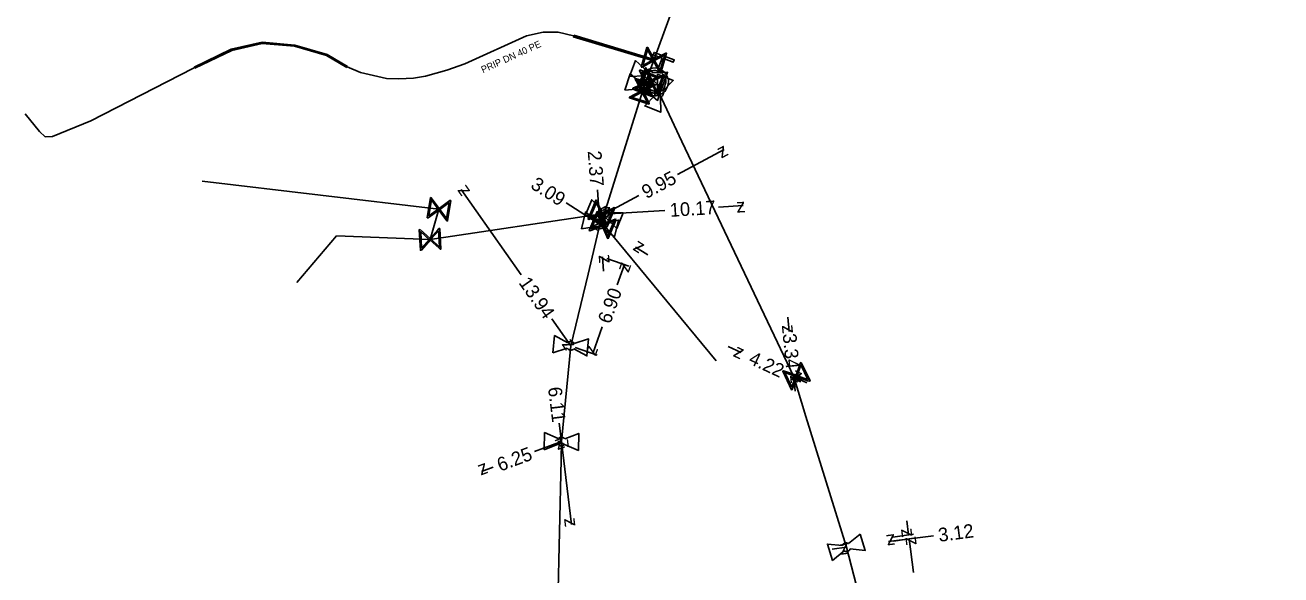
# Model space of a CAD drawing. Extents: x -638315 to -636370, y -1116147 to -1115110.
# Drawn here: x -637156.1 to -637064.4, y -1115769.8 to -1115729.6 of the extents above; entities that cross this region are included whole.
import ezdxf

# ---------------------------------------------------------------- set-up
doc = ezdxf.new("R2010")
doc.units = 0
for name, color, linetype in [('Default', 7, 'Continuous'), ('VP Chránička', 7, 'Continuous'), ('VP Chránička - okraje', 7, 'Continuous'), ('VP Hydrant', 7, 'Continuous'), ('VP Kótování', 7, 'Continuous'), ('VP Lomový bod', 7, 'Continuous'), ('VP Popis přípojky', 7, 'Continuous'), ('VP Přípojka', 7, 'Continuous'), ('VP Řad', 7, 'Continuous'), ('VP Šoupě', 7, 'Continuous')]:
    doc.layers.add(name, color=color, linetype=linetype)

msp = doc.modelspace()

# ---------------------------------------------------------------- linework, layer by layer
at = {"layer": 'Default'}
for points in [[(-637109.703, -1115732.85), (-637109.377, -1115733.004), (-637109.227, -1115733.338), (-637109.058, -1115733.715), (-637109.205, -1115734.104), (-637109.351, -1115734.492), (-637109.728, -1115734.662), (-637110.105, -1115734.832), (-637110.494, -1115734.685), (-637110.88, -1115734.54), (-637111.051, -1115734.164), (-637111.222, -1115733.787), (-637111.076, -1115733.4), (-637110.93, -1115733.01), (-637110.554, -1115732.839), (-637110.221, -1115732.685), (-637109.875, -1115732.786)], [(-637109.855, -1115732.987), (-637110.171, -1115732.868), (-637110.477, -1115733.007), (-637110.782, -1115733.145), (-637110.901, -1115733.462), (-637111.02, -1115733.778), (-637110.882, -1115734.083), (-637110.743, -1115734.389), (-637110.427, -1115734.508), (-637110.113, -1115734.626), (-637109.806, -1115734.488), (-637109.5, -1115734.35), (-637109.381, -1115734.034), (-637109.262, -1115733.718), (-637109.4, -1115733.412), (-637109.539, -1115733.106), (-637109.855, -1115732.987)], [(-637110.417, -1115733.483), (-637110.463, -1115733.509), (-637110.517, -1115733.518), (-637110.6, -1115733.531), (-637110.677, -1115733.503), (-637110.754, -1115733.475), (-637110.81, -1115733.409), (-637110.845, -1115733.369), (-637110.863, -1115733.32)], [(-637110.723, -1115732.935), (-637110.677, -1115732.911), (-637110.625, -1115732.901), (-637110.539, -1115732.888), (-637110.463, -1115732.916), (-637110.386, -1115732.944), (-637110.331, -1115733.009), (-637110.296, -1115733.05), (-637110.277, -1115733.1)], [(-637110.754, -1115734.405), (-637110.799, -1115734.434), (-637110.853, -1115734.445), (-637110.935, -1115734.463), (-637111.013, -1115734.439), (-637111.091, -1115734.414), (-637111.15, -1115734.351), (-637111.187, -1115734.313), (-637111.208, -1115734.264)], [(-637111.086, -1115733.874), (-637111.042, -1115733.847), (-637110.989, -1115733.835), (-637110.905, -1115733.818), (-637110.827, -1115733.842), (-637110.749, -1115733.866), (-637110.691, -1115733.928), (-637110.654, -1115733.968), (-637110.633, -1115734.016)], [(-637110.087, -1115734.725), (-637110.112, -1115734.678), (-637110.119, -1115734.624), (-637110.131, -1115734.54), (-637110.101, -1115734.464), (-637110.071, -1115734.388), (-637110.003, -1115734.334), (-637109.962, -1115734.3), (-637109.912, -1115734.283)], [(-637109.532, -1115734.434), (-637109.508, -1115734.48), (-637109.5, -1115734.533), (-637109.49, -1115734.619), (-637109.52, -1115734.695), (-637109.55, -1115734.771), (-637109.616, -1115734.824), (-637109.658, -1115734.858), (-637109.708, -1115734.875)], [(-637113.675, -1115743.697), (-637113.722, -1115743.721), (-637113.776, -1115743.727), (-637113.86, -1115743.738), (-637113.935, -1115743.707), (-637114.011, -1115743.675), (-637114.064, -1115743.607), (-637114.097, -1115743.565), (-637114.113, -1115743.515)], [(-637113.957, -1115743.137), (-637113.91, -1115743.114), (-637113.857, -1115743.107), (-637113.771, -1115743.098), (-637113.696, -1115743.129), (-637113.62, -1115743.16), (-637113.569, -1115743.227), (-637113.535, -1115743.27), (-637113.519, -1115743.32)], [(-637113.942, -1115744.418), (-637113.985, -1115744.449), (-637114.037, -1115744.464), (-637114.118, -1115744.487), (-637114.198, -1115744.468), (-637114.277, -1115744.449), (-637114.341, -1115744.39), (-637114.38, -1115744.354), (-637114.404, -1115744.307)], [(-637114.308, -1115743.909), (-637114.266, -1115743.879), (-637114.214, -1115743.864), (-637114.131, -1115743.841), (-637114.051, -1115743.86), (-637113.972, -1115743.879), (-637113.91, -1115743.937), (-637113.87, -1115743.974), (-637113.847, -1115744.021)], [(-637116.477, -1115752.803), (-637116.439, -1115752.767), (-637116.391, -1115752.745), (-637116.311, -1115752.711), (-637116.23, -1115752.719), (-637116.148, -1115752.727), (-637116.08, -1115752.775), (-637116.035, -1115752.806), (-637116.005, -1115752.85)], [(-637116.044, -1115753.256), (-637116.082, -1115753.292), (-637116.132, -1115753.315), (-637116.209, -1115753.349), (-637116.29, -1115753.341), (-637116.372, -1115753.333), (-637116.443, -1115753.283), (-637116.487, -1115753.253), (-637116.517, -1115753.21)], [(-637117.174, -1115759.81), (-637117.139, -1115759.771), (-637117.092, -1115759.746), (-637117.015, -1115759.706), (-637116.933, -1115759.707), (-637116.852, -1115759.709), (-637116.779, -1115759.752), (-637116.732, -1115759.78), (-637116.699, -1115759.821)], [(-637116.708, -1115760.229), (-637116.743, -1115760.268), (-637116.791, -1115760.294), (-637116.865, -1115760.334), (-637116.947, -1115760.332), (-637117.029, -1115760.331), (-637117.104, -1115760.286), (-637117.149, -1115760.26), (-637117.183, -1115760.218)], [(-637096.416, -1115767.615), (-637096.395, -1115767.566), (-637096.358, -1115767.526), (-637096.3, -1115767.465), (-637096.222, -1115767.441), (-637096.144, -1115767.417), (-637096.059, -1115767.435), (-637096.007, -1115767.446), (-637095.963, -1115767.475)], [(-637095.842, -1115767.865), (-637095.863, -1115767.913), (-637095.899, -1115767.952), (-637095.959, -1115768.014), (-637096.038, -1115768.038), (-637096.116, -1115768.062), (-637096.198, -1115768.044), (-637096.251, -1115768.033), (-637096.296, -1115768.004)]]:
    msp.add_open_spline(points, degree=3, dxfattribs=at)
at = {"layer": 'VP Chránička'}
for points in [[(-637110.19, -1115732.169), (-637116.06, -1115730.4)], [(-637132.58, -1115732.66), (-637134.08, -1115731.79), (-637136.42, -1115731.11), (-637138.79, -1115730.91), (-637141.04, -1115731.41), (-637143.74, -1115732.71)]]:
    msp.add_lwpolyline(points, dxfattribs=at)
at = {"layer": 'VP Chránička - okraje'}
for points in [[(-637110.206, -1115732.222), (-637116.076, -1115730.453)], [(-637116.044, -1115730.347), (-637110.174, -1115732.116)], [(-637143.76, -1115732.669), (-637141.055, -1115731.367), (-637138.793, -1115730.865), (-637136.412, -1115731.066), (-637134.062, -1115731.748), (-637132.557, -1115732.621)], [(-637132.603, -1115732.699), (-637134.098, -1115731.832), (-637136.428, -1115731.154), (-637138.787, -1115730.955), (-637141.025, -1115731.453), (-637143.72, -1115732.751)]]:
    msp.add_lwpolyline(points, dxfattribs=at)
at = {"layer": 'VP Hydrant'}
msp.add_lwpolyline([(-637109.875, -1115732.786), (-637109.586, -1115732.018), (-637110.231, -1115731.775), (-637110.167, -1115731.603), (-637108.704, -1115732.154), (-637108.769, -1115732.325), (-637109.414, -1115732.083), (-637109.703, -1115732.85)], dxfattribs=at)
at = {"layer": 'VP Kótování'}
for points in [[(-637108.455, -1115740.523), (-637105.06, -1115738.69)], [(-637119.892, -1115747.856), (-637124.268, -1115741.62)], [(-637114.312, -1115741.63), (-637114.125, -1115744.164)], [(-637116.584, -1115742.592), (-637114.125, -1115744.164)], [(-637111.279, -1115742.048), (-637113.816, -1115743.418)], [(-637109.376, -1115743.139), (-637113.816, -1115743.418)], [(-637105.475, -1115742.894), (-637103.67, -1115742.78)], [(-637110.635, -1115746.396), (-637111.52, -1115745.83)], [(-637113.873, -1115747.577), (-637113.95, -1115746.53)], [(-637113.62, -1115746.647), (-637112.015, -1115747.218)], [(-637112.867, -1115748.57), (-637112.344, -1115747.101)], [(-637100.404, -1115750.935), (-637100.3, -1115751.98)], [(-637117.646, -1115751.055), (-637116.26, -1115753.03)], [(-637113.96, -1115751.645), (-637114.654, -1115753.601)], [(-637115.93, -1115753.147), (-637114.325, -1115753.718)], [(-637104.752, -1115753.077), (-637103.8, -1115753.52)], [(-637099.867, -1115756.346), (-637099.971, -1115755.301)], [(-637099.019, -1115755.744), (-637099.971, -1115755.301)], [(-637117.103, -1115758.688), (-637116.94, -1115760.02)], [(-637118.912, -1115760.758), (-637116.94, -1115760.02)], [(-637116.94, -1115760.02), (-637116.2, -1115766.08)], [(-637121.919, -1115761.884), (-637122.79, -1115762.21)], [(-637091.723, -1115765.8), (-637091.584, -1115766.841)], [(-637089.763, -1115766.901), (-637093.041, -1115767.333)], [(-637092.733, -1115766.994), (-637091.237, -1115766.795)], [(-637092.694, -1115767.287), (-637091.198, -1115767.088)], [(-637091.22, -1115769.577), (-637091.545, -1115767.134)], [(-637097.171, -1115767.877), (-637096.13, -1115767.74)]]:
    msp.add_lwpolyline(points, dxfattribs=at)
at = {"layer": 'VP Lomový bod'}
for points in [[(-637111.958, -1115733.368), (-637111.529, -1115732.194), (-637110.723, -1115732.935)], [(-637112.299, -1115734.364), (-637111.927, -1115733.171), (-637111.086, -1115733.874)], [(-637110.863, -1115733.32), (-637111.958, -1115733.368)], [(-637110.277, -1115733.1), (-637109.181, -1115733.052), (-637109.61, -1115734.226), (-637110.417, -1115733.483)], [(-637109.931, -1115733.187), (-637108.769, -1115733.648), (-637109.532, -1115734.434)], [(-637109.912, -1115734.283), (-637109.931, -1115733.187)], [(-637111.208, -1115734.264), (-637112.299, -1115734.364)], [(-637110.633, -1115734.016), (-637109.54, -1115733.916), (-637109.913, -1115735.109), (-637110.754, -1115734.405)], [(-637109.708, -1115734.875), (-637109.69, -1115735.972), (-637110.852, -1115735.511), (-637110.087, -1115734.725)], [(-637115.21, -1115743.517), (-637114.731, -1115742.362), (-637113.957, -1115743.137)], [(-637115.486, -1115744.479), (-637115.194, -1115743.264), (-637114.308, -1115743.909)], [(-637114.113, -1115743.515), (-637115.21, -1115743.517)], [(-637113.519, -1115743.32), (-637112.421, -1115743.319), (-637112.9, -1115744.474), (-637113.675, -1115743.697)], [(-637114.404, -1115744.307), (-637115.486, -1115744.479)], [(-637113.847, -1115744.021), (-637112.763, -1115743.849), (-637113.056, -1115745.064), (-637113.942, -1115744.418)], [(-637117.565, -1115753.531), (-637117.444, -1115752.287), (-637116.477, -1115752.803)], [(-637116.005, -1115752.85), (-637114.955, -1115752.529), (-637115.076, -1115753.773), (-637116.044, -1115753.256)], [(-637116.517, -1115753.21), (-637117.565, -1115753.531)], [(-637118.204, -1115760.617), (-637118.176, -1115759.368), (-637117.174, -1115759.81)], [(-637116.699, -1115759.821), (-637115.677, -1115759.422), (-637115.704, -1115760.672), (-637116.708, -1115760.229)], [(-637117.183, -1115760.218), (-637118.204, -1115760.617)], [(-637095.963, -1115767.475), (-637095.12, -1115766.774)], [(-637095.12, -1115766.774), (-637094.751, -1115767.968), (-637095.842, -1115767.865)], [(-637096.296, -1115768.004), (-637097.14, -1115768.706), (-637097.509, -1115767.511), (-637096.416, -1115767.615)]]:
    msp.add_lwpolyline(points, dxfattribs=at)
at = {"layer": 'VP Přípojka'}
for points in [[(-637110.19, -1115732.169), (-637116.06, -1115730.4), (-637117.18, -1115730.13), (-637118.27, -1115730.12), (-637119.49, -1115730.38), (-637124, -1115732.43), (-637125.32, -1115732.9), (-637126.87, -1115733.33), (-637127.75, -1115733.48), (-637128.82, -1115733.53), (-637129.72, -1115733.5), (-637131.62, -1115733.08), (-637132.58, -1115732.66), (-637134.08, -1115731.79), (-637136.42, -1115731.11), (-637138.79, -1115730.91), (-637141.04, -1115731.41), (-637143.851, -1115732.785), (-637151.32, -1115736.61), (-637154.12, -1115737.75), (-637154.64, -1115737.76), (-637155.05, -1115737.39), (-637156.112, -1115736.094)], [(-637110.14, -1115733.75), (-637110.36, -1115733.69), (-637110.707, -1115733.574)], [(-637126.532, -1115745.255), (-637125.883, -1115743.057), (-637143.188, -1115741.007)], [(-637113.816, -1115743.418), (-637114.135, -1115743.404), (-637126.532, -1115745.255), (-637133.361, -1115744.997), (-637136.258, -1115748.414)], [(-637113.816, -1115743.418), (-637114.01, -1115743.37)], [(-637113.93, -1115744.21), (-637114.125, -1115744.164)], [(-637105.646, -1115754.123), (-637113.781, -1115744.293), (-637114.125, -1115744.164)], [(-637099.971, -1115755.301), (-637099.78, -1115755.24)]]:
    msp.add_lwpolyline(points, dxfattribs=at)
at = {"layer": 'VP Řad'}
for points in [[(-637109.13, -1115705.79), (-637107.36, -1115707.69), (-637103.37, -1115712.34), (-637103.079, -1115712.719), (-637103.247, -1115713.179), (-637110.19, -1115732.169), (-637110.57, -1115733.21), (-637110.92, -1115734.14)], [(-637119.99, -1115832.377), (-637120.35, -1115823.44), (-637118.093, -1115812.674), (-637117.308, -1115805.96), (-637116.17, -1115792.77), (-637116.64, -1115779.48), (-637117.2, -1115771.88), (-637116.969, -1115761.358), (-637116.969, -1115761.353), (-637116.94, -1115760.02), (-637116.26, -1115753.03), (-637114.999, -1115747.795), (-637114.125, -1115744.164), (-637113.816, -1115743.418), (-637110.92, -1115734.14)], [(-637110.92, -1115734.14), (-637109.81, -1115734.58), (-637108.135, -1115738.107), (-637099.971, -1115755.301), (-637099.078, -1115758.192), (-637096.13, -1115767.74), (-637094.676, -1115773.277), (-637092.522, -1115780.838), (-637090.98, -1115786.25), (-637087.35, -1115797.43), (-637085.55, -1115802.69), (-637083.45, -1115808.11), (-637079.33, -1115815.7), (-637074.96, -1115821.37), (-637064.392, -1115832.177)]]:
    msp.add_lwpolyline(points, dxfattribs=at)
at = {"layer": 'VP Šoupě'}
for points in [[(-637111.125, -1115732.671), (-637110.692, -1115731.234), (-637110.629, -1115731.254), (-637110.571, -1115731.369), (-637110.173, -1115732.108), (-637109.319, -1115731.648), (-637109.255, -1115731.667), (-637109.688, -1115733.104), (-637109.751, -1115733.084), (-637110.209, -1115732.227), (-637110.949, -1115732.626), (-637111.061, -1115732.69), (-637111.125, -1115732.671)], [(-637110.989, -1115732.547), (-637110.251, -1115732.15), (-637110.648, -1115731.413), (-637110.989, -1115732.547)], [(-637109.389, -1115731.786), (-637110.132, -1115732.186), (-637109.733, -1115732.926), (-637109.389, -1115731.786)], [(-637111.533, -1115733.5), (-637110.101, -1115733.947), (-637110.121, -1115734.01), (-637110.236, -1115734.066), (-637110.98, -1115734.457), (-637110.528, -1115735.316), (-637110.548, -1115735.379), (-637111.98, -1115734.932), (-637111.96, -1115734.869), (-637111.099, -1115734.42), (-637111.49, -1115733.676), (-637111.553, -1115733.563), (-637111.533, -1115733.5)], [(-637111.208, -1115732.884), (-637109.804, -1115733.412), (-637109.827, -1115733.474), (-637109.946, -1115733.523), (-637110.71, -1115733.871), (-637110.309, -1115734.754), (-637110.332, -1115734.816), (-637111.736, -1115734.288), (-637111.713, -1115734.226), (-637110.827, -1115733.827), (-637111.174, -1115733.062), (-637111.231, -1115732.945), (-637111.208, -1115732.884)], [(-637109.403, -1115733.249), (-637109.931, -1115734.653), (-637109.993, -1115734.63), (-637110.042, -1115734.511), (-637110.39, -1115733.747), (-637111.273, -1115734.148), (-637111.335, -1115734.125), (-637110.807, -1115732.721), (-637110.745, -1115732.744), (-637110.346, -1115733.63), (-637109.581, -1115733.283), (-637109.464, -1115733.226), (-637109.403, -1115733.249)], [(-637111.194, -1115734.015), (-637110.426, -1115733.667), (-637110.774, -1115732.901), (-637111.194, -1115734.015)], [(-637111.093, -1115733.027), (-637110.747, -1115733.791), (-637109.985, -1115733.444), (-637111.093, -1115733.027)], [(-637109.546, -1115733.364), (-637110.31, -1115733.71), (-637109.963, -1115734.472), (-637109.546, -1115733.364)], [(-637110.442, -1115734.675), (-637110.79, -1115733.907), (-637111.556, -1115734.255), (-637110.442, -1115734.675)], [(-637111.411, -1115733.637), (-637111.021, -1115734.379), (-637110.28, -1115733.989), (-637111.411, -1115733.637)], [(-637110.665, -1115735.244), (-637111.058, -1115734.498), (-637111.802, -1115734.889), (-637110.665, -1115735.244)], [(-637125.027, -1115742.43), (-637125.256, -1115743.912), (-637125.321, -1115743.902), (-637125.394, -1115743.796), (-637125.891, -1115743.119), (-637126.674, -1115743.693), (-637126.739, -1115743.683), (-637126.51, -1115742.201), (-637126.445, -1115742.211), (-637125.872, -1115742.996), (-637125.195, -1115742.499), (-637125.092, -1115742.42), (-637125.027, -1115742.43)], [(-637126.623, -1115743.547), (-637125.943, -1115743.048), (-637126.441, -1115742.37), (-637126.623, -1115743.547)], [(-637125.144, -1115742.571), (-637125.82, -1115743.067), (-637125.325, -1115743.742), (-637125.144, -1115742.571)], [(-637113.03, -1115742.964), (-637113.604, -1115744.35), (-637113.665, -1115744.325), (-637113.71, -1115744.205), (-637114.033, -1115743.429), (-637114.929, -1115743.801), (-637114.99, -1115743.776), (-637114.416, -1115742.39), (-637114.355, -1115742.415), (-637113.985, -1115743.314), (-637113.209, -1115742.991), (-637113.091, -1115742.939), (-637113.03, -1115742.964)], [(-637114.845, -1115743.671), (-637114.067, -1115743.348), (-637114.389, -1115742.571), (-637114.845, -1115743.671)], [(-637112.95, -1115743.804), (-637113.524, -1115745.19), (-637113.585, -1115745.165), (-637113.63, -1115745.045), (-637113.953, -1115744.269), (-637114.849, -1115744.641), (-637114.91, -1115744.616), (-637114.336, -1115743.23), (-637114.275, -1115743.255), (-637113.905, -1115744.154), (-637113.129, -1115743.831), (-637113.011, -1115743.779), (-637112.95, -1115743.804)], [(-637114.765, -1115744.511), (-637113.987, -1115744.188), (-637114.309, -1115743.411), (-637114.765, -1115744.511)], [(-637113.177, -1115743.074), (-637113.951, -1115743.395), (-637113.63, -1115744.168), (-637113.177, -1115743.074)], [(-637125.826, -1115744.463), (-637125.74, -1115745.961), (-637125.806, -1115745.964), (-637125.899, -1115745.876), (-637126.527, -1115745.318), (-637127.172, -1115746.043), (-637127.238, -1115746.046), (-637127.323, -1115744.549), (-637127.257, -1115744.545), (-637126.534, -1115745.193), (-637125.975, -1115744.566), (-637125.892, -1115744.467), (-637125.826, -1115744.463)], [(-637113.097, -1115743.914), (-637113.871, -1115744.235), (-637113.55, -1115745.008), (-637113.097, -1115743.914)], [(-637127.153, -1115745.889), (-637126.592, -1115745.259), (-637127.221, -1115744.7), (-637127.153, -1115745.889)], [(-637125.91, -1115744.626), (-637126.468, -1115745.252), (-637125.843, -1115745.808), (-637125.91, -1115744.626)], [(-637099.424, -1115754.241), (-637098.781, -1115755.596), (-637098.841, -1115755.624), (-637098.96, -1115755.577), (-637099.752, -1115755.296), (-637100.076, -1115756.211), (-637100.136, -1115756.239), (-637100.779, -1115754.884), (-637100.72, -1115754.856), (-637099.805, -1115755.184), (-637099.524, -1115754.392), (-637099.484, -1115754.269), (-637099.424, -1115754.241)], [(-637099.442, -1115754.423), (-637099.722, -1115755.213), (-637098.934, -1115755.493), (-637099.442, -1115754.423)], [(-637100.117, -1115756.061), (-637099.835, -1115755.267), (-637100.627, -1115754.985), (-637100.117, -1115756.061)]]:
    msp.add_lwpolyline(points, dxfattribs=at)

# ---------------------------------------------------------------- texts
at = {"layer": 'VP Kótování'}
for s, rotation, p in [('2.37', 274.23015, (-637115.022, -1115738.817)), ('z', 28.36783, (-637105.262, -1115739.368)), ('3.09', 327.39949, (-637119.261, -1115741.473)), ('9.95', 28.36783, (-637110.734, -1115742.322)), ('z', 125.06271, (-637123.572, -1115741.742)), ('10.17', 3.59812, (-637108.995, -1115743.616)), ('z', 3.59812, (-637104.138, -1115743.31)), ('z', 208.36781, (-637113.614, -1115742.74)), ('z', 183.59816, (-637113.348, -1115742.888)), ('z', 327.3995, (-637114.816, -1115744.316)), ('z', 274.23017, (-637114.661, -1115743.702)), ('z', 147.39947, (-637110.829, -1115745.678)), ('z', 94.23013, (-637113.414, -1115746.992)), ('z', 70.43559, (-637112.041, -1115747.739)), ('13.94', 305.06273, (-637120.1, -1115748.429)), ('6.90', 70.43559, (-637113.371, -1115751.483)), ('z', 275.65763, (-637100.847, -1115751.532)), ('z', 305.06274, (-637116.956, -1115752.908)), ('3.34', 275.65762, (-637100.783, -1115752.176)), ('z', 250.43557, (-637114.958, -1115752.962)), ('z', 335.05525, (-637104.464, -1115753.762)), ('4.22', 335.05523, (-637103.339, -1115754.286)), ('z', 95.65765, (-637099.424, -1115755.749)), ('z', 155.05521, (-637099.307, -1115755.059)), ('6.11', 276.96207, (-637117.924, -1115756.085)), ('z', 20.52386, (-637117.233, -1115760.664)), ('z', 96.96205, (-637116.383, -1115760.456)), ('6.25', 20.52386, (-637121.416, -1115762.229)), ('z', 200.52384, (-637122.497, -1115761.566)), ('z', 276.96203, (-637116.757, -1115765.644)), ('z', 277.58185, (-637092.146, -1115766.411)), ('3.12', 7.50592, (-637089.35, -1115767.351)), ('z', 187.50596, (-637092.611, -1115766.772)), ('z', 97.58182, (-637090.984, -1115767.564)), ('z', 7.50592, (-637096.56, -1115768.301))]:
    msp.add_text(s, height=1, rotation=rotation, dxfattribs=at).set_placement(p)
at = {"layer": 'VP Popis přípojky'}
msp.add_text('PRIP DN 40 PE', height=0.5, rotation=24.44395, dxfattribs=at).set_placement((-637122.669, -1115733.124))

doc.saveas('drawing.dxf')
